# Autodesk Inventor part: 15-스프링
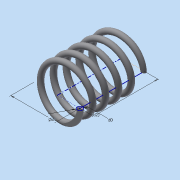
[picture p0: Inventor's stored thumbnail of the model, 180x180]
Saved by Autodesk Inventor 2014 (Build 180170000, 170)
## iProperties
Created: 2016-01
Part Number: 15-스프링
Material: 강철, 탄소
Document SubType Name: Modeling
Designer: Administrator
Density: 7.87 g/cm^3
Appearance: 반연마
Mass: 6.46669 g
Surface Area: 16.7182 cm^2
Volume: 0.821689 cm^3
Author: Administrator
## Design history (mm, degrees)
sketch "스케치1"
  geometry: L1 (0, 0)-(0, 20.5); L2 (0, 20.5)-(8.5, 20.5); L3 (8.5, 20.5)-(8.5, 0); L4 (8.5, 0)-(0, 0); C1 r 1 at (8.5, 0)
  constraints: 8 end point, 2 parallel, 1 centre point, 1 coincident, 1 perpendicular, 1 vertical
  dimensions: "d0" = 2 diameter of C1; "d1" = 17 diameter of L3 L1; "d2" = 20.5 distance between parallel lines of L4 L2 (derived)
feature "코일1" pitch "d3" = 10; turns "d5" = 5; dims "d4" = 20.5 (= d2), "d6" = 0, angle "d7" = 90 deg, angle "d8" = 90 deg, "d9" = 0, "d10" = 0
node "작업 평면1"
sketch "스케치2"
  geometry: L1 (-9.5, 0)-(-7.5, 0) reference; L2 (-9.5, 0)-(-7.5, 0) reference; 1 further point
  constraints: 2 horizontal alignment
extrude "돌출1" cut sketch "스케치2" distance "d12" = 10; taper "d13" = 0 deg
node "작업 평면2"
sketch "스케치3"
  geometry: L1 (-7.5, 0)-(-9.5, 0) reference; 1 further point
  constraints: 1 horizontal alignment
extrude "돌출2" cut sketch "스케치3" distance "d15" = 10; taper "d16" = 0 deg
node "솔리드1"
node "절단 모서리 투영1"
node "절단 모서리 투영2"
node "절단 모서리 투영3"
other parameters: "d11" = 0, "d14" = 20.5 (= d2)
